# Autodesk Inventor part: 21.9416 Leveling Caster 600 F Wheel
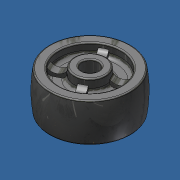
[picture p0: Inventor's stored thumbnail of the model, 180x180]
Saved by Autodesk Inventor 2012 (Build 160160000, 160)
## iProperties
Created: 2015-01
Part Number: 21.9416 Leveling Caster 600 F Wheel
Material: Phenolic
Document SubType Name: Modeling
Designer: Admin
Density: 1.38 g/cm^3
Mass: 93.6767 g
Surface Area: 161.254 cm^2
Volume: 67.8817 cm^3
Author: Admin
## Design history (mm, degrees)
feature "Base1"
body "Solid1"
